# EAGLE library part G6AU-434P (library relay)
RELAY 4 x switch, single coil latching, 0.3 A/125 V AC, 1 A/30 V DC, Omron
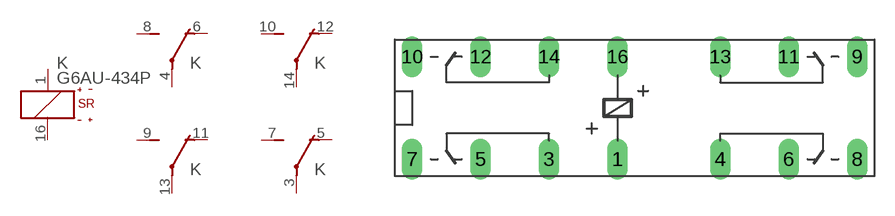
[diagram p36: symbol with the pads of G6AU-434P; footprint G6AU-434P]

Designator prefix K; gates -RS=K+-S-+R -1=U -2=U -3=U -4=U

## G6AU-434P (OC_FARNELL: unknown; OC_NEWARK: unknown)  [G6AU-434P]
1  -RS:+  pas
3  -4:P  pas
4  -1:P  pas
5  -4:O  pas
6  -1:O  pas
7  -4:S  pas
8  -1:S  pas
9  -2:S  pas
10  -3:S  pas
11  -2:O  pas
12  -3:O  pas
13  -2:P  pas
14  -3:P  pas
16  -RS:-  pas

## Footprint G6AU-434P (pad centres in mm)
RELAY 4 x switch, single coil latching, 0.3 A/125 V AC, 1 A/30 V DC, Omron
drill 1.016 long: 1 -1.27,-3.81; 3 -6.35,-3.81; 4 6.35,-3.81; 5 -11.43,-3.81; 6 11.43,-3.81; 7 -16.51,-3.81; 8 16.51,-3.81; 9 16.51,3.81; 10 -16.51,3.81; 11 11.43,3.81; 12 -11.43,3.81; 13 6.35,3.81; 14 -6.35,3.81; 16 -1.27,3.81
